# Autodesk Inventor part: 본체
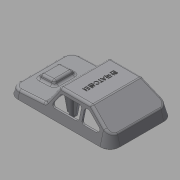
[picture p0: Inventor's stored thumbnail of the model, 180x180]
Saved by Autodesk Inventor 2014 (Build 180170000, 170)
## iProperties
Created: 2015-05
Part Number: 본체
Material: Generic
Document SubType Name: Modeling
Designer: Administrator
Density: 1 g/cm^3
Appearance: Default
Author: Administrator
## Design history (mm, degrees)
sketch "스케치1"
  geometry: L1 (-49, -38)-(49, -38); L2 (61, -26)-(61, 26); L3 (49, 38)-(-49, 38); L4 (-61, 26)-(-61, -26); L5 (-61, -38)-(61, 38); L6 (61, -38)-(-61, 38); A1 r 12 centre (-49, 26) between (-49, 38) and (-61, 26); A2 r 12 centre (-49, -26) between (-61, -26) and (-49, -38); A3 r 12 centre (49, -26) between (49, -38) and (61, -26); A4 r 12 centre (49, 26) between (61, 26) and (49, 38); 3 further points
  constraints: 12 end point, 8 point on circle, 8 point on line, 8 tangent, 4 centre point, 3 equal radius, 3 midpoint, 2 parallel, 1 coincident, 1 horizontal, 1 perpendicular
  dimensions: "d0" = 122 distance of L5.end L6.end; "d1" = 76 distance of L6.start L5.end; "d2" = 12 radius of A1
extrude "돌출1" new body sketch "스케치1" distance "d3" = 30; taper "d4" = -15 deg
sketch "스케치2"
  geometry: L1 (49, 30)-(-49, 30) reference; L2 (-61, 0)-(-52.962, 30) reference; L3 (49, 0)-(-49, 0) reference; L4 (-61, 0)-(-49, 0) reference; L5 (-52.962, 30)-(-49, 30) reference; L6 (-31, 30)-(-61, 10); L7 (-61, 10)-(-61, 30); L8 (-61, 30)-(-31, 30); 1 further point
  constraints: 6 end point, 2 perpendicular, 1 collinear, 1 vertical alignment
  dimensions: "d5" = 20 distance of L6.end L7.end; "d6" = 30 distance of L7.end L6.start
extrude "돌출2" cut sketch "스케치2" stored distance "d7" = 30; taper "d8" = 0 deg
sketch "스케치3"
  geometry: L1 (49, 0)-(61, 0) reference; L2 (61, 0)-(52.962, 30) reference; L3 (49, 30)-(-31, 30) reference; L4 (49, 30)-(52.962, 30) reference; L5 (49, 0)-(-49, 0) reference; L6 (61, 8)-(19, 10.201); L7 (19, 10.201)-(6.628, 30); L8 (6.628, 30)-(61, 30); L9 (61, 30)-(61, 8); 1 further point
  constraints: 8 end point, 1 collinear, 1 parallel, 1 perpendicular, 1 vertical alignment
  dimensions: "d10" = 125 deg angle of L7 L6; "d11" = 3 deg angle of L6 L5; "d12" = 8 distance of L6.start L1.end; "d13" = 42 horizontal distance of L6.end L6.start
extrude "돌출3" cut sketch "스케치3" stored distance "d14" = 30; taper "d15" = 0 deg
sketch "스케치4"
  geometry: L1 (-42.476, 9.267)-(-42.476, 61.267) reference; L2 (-31.476, 48.267)-(-11.476, 48.267); L3 (-11.476, 48.267)-(-11.476, 22.267); L4 (-11.476, 22.267)-(-31.476, 22.267); L5 (-31.476, 22.267)-(-31.476, 48.267); 3 further points
  constraints: 8 end point, 2 midpoint, 2 parallel, 1 horizontal, 1 horizontal alignment, 1 perpendicular
  dimensions: "d16" = 26 distance of L2.end L3.end; "d17" = 20 distance of L3.end L4.end; "d18" = 11 distance between parallel lines of L1 L5
extrude "돌출4" join sketch "스케치4" distance "d19" = 5; taper "d20" = -20 deg
fillet "모깎기1" dims "d21" = 3
fillet "모깎기2" dims "d22" = 3
fillet "모깎기3" dims "d23" = 3
fillet "모깎기4" dims "d24" = 3
feature "쉘1" dims "d25" = 2
sketch "스케치5"
  geometry: L1 (-49, 35.929)-(49, 35.929) reference; L2 (58.929, 26)-(58.929, -26) reference; L3 (49, -35.929)-(-49, -35.929) reference; L4 (-58.929, -26)-(-58.929, 26) reference; L5 (49, 36.929)-(-49, 36.929); L6 (-59.929, 26)-(-59.929, -26); L7 (-49, -36.929)-(49, -36.929); L8 (59.929, -26)-(59.929, 26); A1 r 9.929 centre (49, 26) between (58.929, 26) and (49, 35.929) reference; A2 r 9.929 centre (49, -26) between (49, -35.929) and (58.929, -26) reference; A3 r 9.929 centre (-49, -26) between (-58.929, -26) and (-49, -35.929) reference; A4 r 9.929 centre (-49, 26) between (-49, 35.929) and (-58.929, 26) reference; A5 r 10.929 centre (-49, 26) between (-49, 36.929) and (-59.929, 26); A6 r 10.929 centre (-49, -26) between (-59.929, -26) and (-49, -36.929); A7 r 10.929 centre (49, -26) between (49, -36.929) and (59.929, -26); A8 r 10.929 centre (49, 26) between (59.929, 26) and (49, 36.929); 1 further point
  constraints: 8 end point, 8 point on circle, 4 centre point, 7 other
  dimensions: "d26" = 1 distance between parallel lines of L5 L1
extrude "돌출5" join sketch "스케치5" distance "d27" = 1; taper "d28" = 0 deg
sketch "스케치6"
  geometry: L1 (18.172, 11.526)-(7.51, 28.59) reference; L2 (4.965, 30)-(-30.092, 30) reference; L3 (-31.756, 29.496)-(-50.664, 16.891) reference; L4 (10.362, 14.59)-(4.738, 23.59); L5 (2.194, 25)-(-17.77, 25); L6 (-20.77, 13)-(-20.77, 22); L7 (7.818, 10)-(-17.77, 10); L8 (-30.242, 24.496)-(-43.742, 15.496); L9 (-26.986, 25)-(-28.578, 25); L10 (-23.986, 22)-(-23.986, 13); L11 (-26.986, 10)-(-42.078, 10); A1 r 3 centre (7.818, 13) between (7.818, 10) and (10.362, 14.59); A2 r 3 centre (2.194, 22) between (4.738, 23.59) and (2.194, 25); A3 r 3 centre (-17.77, 22) between (-17.77, 25) and (-20.77, 22); A4 r 3 centre (-17.77, 13) between (-20.77, 13) and (-17.77, 10); A5 r 3 centre (-26.986, 13) between (-26.986, 10) and (-23.986, 13); A6 r 3 centre (-26.986, 22) between (-23.986, 22) and (-26.986, 25); A7 r 3 centre (-28.578, 22) between (-28.578, 25) and (-30.242, 24.496); A8 r 3 centre (-42.078, 13) between (-43.742, 15.496) and (-42.078, 10); 7 further points
  constraints: 16 end point, 16 point on circle, 16 tangent, 12 point on line, 8 centre point, 7 equal radius, 5 parallel, 3 perpendicular
  dimensions: "d29" = 5 distance between parallel lines of L2 L5; "d30" = 5 distance between parallel lines of L1 L4; "d31" = 34 distance of point (13.23, 10) point (-20.77, 10); "d32" = 15 distance of point (-20.77, 10) point (-20.77, 25); "d33" = 5 distance between parallel lines of L3 L8; "d34" = 5 distance between parallel lines of L2 L9; "d35" = 15 distance of point (-23.986, 25) point (-23.986, 10); "d36" = 28 distance of point (-23.986, 10) point (-51.986, 10); "d37" = 3 radius of A1
extrude "돌출6" cut sketch "스케치6" stored distance "d38" = 1; taper "d39" = 0 deg
node "작업 평면1"
sketch "스케치7"
  geometry: A1 r 4 centre (21, 0) between (25, 0) and (17, 0); A2 r 4 centre (10, 0) between (14, 0) and (6, 0); A3 r 4 centre (-10, 0) between (-6, 0) and (-14, 0); A4 r 4 centre (-21, 0) between (-17, 0) and (-25, 0); 4 further points
  constraints: 8 point on circle, 4 centre point, 4 horizontal alignment, 14 other
  dimensions: "d41" = 8 diameter of A1; "d42" = 8 diameter of A2; "d43" = 8 diameter of A3; "d44" = 8 diameter of A4; "d45" = 10 distance of A2.centre point (0, 0); "d46" = 20 distance of A3.centre A2.centre; "d47" = 11 distance of A2.centre A1.centre; "d48" = 11 distance of A4.centre A3.centre
extrude "돌출7" join sketch "스케치7" stored distance "d49" = 1; taper "d50" = 0 deg
chamfer "모따기1" distance "d51" = 1; stored, may be unused: second distance "d52" = 2, angle "d53" = 45 deg
sketch "스케치8"
  geometry: C1 r 3 at (-40, 0); C2 r 3 at (40, 0); C3 r 3 at (0, 22); C4 r 3 at (0, -22); 1 further point
  constraints: 4 centre point, 2 horizontal alignment, 2 vertical alignment
  dimensions: "d54" = 6 diameter of C1; "d55" = 6 diameter of C2; "d56" = 6 diameter of C3; "d57" = 6 diameter of C4; "d58" = 40 distance of point (0, 0) C1.centre; "d59" = 40 distance of C2.centre point (0, 0); "d60" = 22 distance of C3.centre point (0, 0); "d61" = 22 distance of point (0, 0) C4.centre
extrude "돌출8" join sketch "스케치8" stored distance "d62" = 1; taper "d63" = 2 deg
node "작업 평면2"
sketch "스케치9"
  geometry: L1 (-45, -1)-(-35, -1); L2 (-35, -1)-(-35, 1); L3 (-35, 1)-(-45, 1); L4 (-45, 1)-(-45, -1); L5 (-45, -1)-(-35, 1); L6 (-35, -1)-(-45, 1); L7 (-5, 21)-(5, 21); L8 (5, 21)-(5, 23); L9 (5, 23)-(-5, 23); L10 (-5, 23)-(-5, 21); L11 (-5, 21)-(5, 23); L12 (5, 21)-(-5, 23); L13 (35, -1)-(45, -1); L14 (45, -1)-(45, 1); L15 (45, 1)-(35, 1); L16 (35, 1)-(35, -1); L17 (35, -1)-(45, 1); L18 (45, -1)-(35, 1); L19 (-5, -23)-(5, -23); L20 (5, -23)-(5, -21); L21 (5, -21)-(-5, -21); L22 (-5, -21)-(-5, -23); L23 (-5, -23)-(5, -21); L24 (5, -23)-(-5, -21); C1 r 3 at (-40, 0) reference; C2 r 3 at (0, 22) reference; C3 r 3 at (40, 0) reference; C4 r 3 at (0, -22) reference; 1 further point
  constraints: 48 end point, 8 midpoint, 8 parallel, 4 horizontal, 4 perpendicular
  dimensions: "d65" = 10 distance of L1.start L1.end; "d66" = 2 distance of L1.end L2.end; "d67" = 10 distance of L7.start L7.end; "d68" = 2 distance of L7.end L8.end; "d69" = 10 distance of L19.start L19.end; "d70" = 2 distance of L19.end L20.end; "d71" = 10 distance of L13.start L13.end; "d72" = 2 distance of L13.end L14.end
extrude "돌출9" join sketch "스케치9" stored distance "d73" = 1; taper "d74" = 2.5 deg
sketch "스케치11"
  geometry: L1 (45, 2)-(45.429, 11.82) reference; L2 (35, 2)-(34.546, 12.39) reference; L3 (43, 0)-(43.07, 2) reference; L4 (37, 0)-(36.93, 2) reference; L5 (46.675, 11.755)-(34.533, 12.391) reference; L6 (47.906, 9.978)-(47.579, 11.049) reference; L7 (45, 2)-(46.72, 11.753); L8 (45.429, 11.82)-(46.72, 11.753); L9 (-49, 0)-(49, 0) reference; L10 (35, 2)-(33.155, 12.463); L11 (34.546, 12.39)-(33.155, 12.463); A1 r 1 centre (46.623, 10.756) between (47.579, 11.049) and (46.675, 11.755) reference; A2 r 5 centre (52.688, 11.44) between (47.906, 9.978) and (52.426, 6.447) reference; 1 further point
  constraints: 8 end point, 3 collinear, 1 point on line
  dimensions: "d76" = 80 deg angle of L7 L9; "d82" = 80 deg angle of L10 L9
extrude "돌출10" join sketch "스케치11" stored distance "d77" = 1; taper "d78" = 0 deg
sketch "스케치12"
  geometry: L1 (-45, 2)-(-46.719, 11.752) reference; L2 (-45.429, 11.82)-(-45, 2) reference; L3 (-46.675, 11.755)-(-45.429, 11.82) reference; A1 r 1 centre (-46.623, 10.756) between (-46.675, 11.755) and (-46.719, 11.752) reference; 1 further point
extrude "돌출11" join sketch "스케치12" stored distance "d79" = 1; taper "d80" = 0 deg
extrude "돌출12" join sketch "스케치11" stored distance "d83" = 1; taper "d84" = 0 deg
extrude "돌출13" join sketch "스케치11" stored distance "d85" = 1; taper "d86" = 0 deg
sketch "스케치13"
  geometry: L1 (-45, 2)-(-45.69, 17.803) reference; L2 (-35, 2)-(-33.969, 25.617) reference; L3 (-35, 2)-(-37.098, 2) reference; L4 (-42.902, 2)-(-45, 2) reference; L5 (49, 0)-(-49, 0) reference; L6 (-49.555, 15.226)-(-30.646, 27.832) reference; L7 (-45, 2)-(-47.566, 16.552); L8 (-35, 2)-(-30.426, 27.943); L9 (-30.092, 28)-(4.965, 28) reference; A1 r 1 centre (-30.092, 27) between (-30.092, 28) and (-30.646, 27.832) reference; 1 further point
  constraints: 4 end point, 1 point on circle, 1 point on line
  dimensions: "d87" = 80 deg angle of L8 L5; "d88" = 80 deg angle of L7 L5
extrude "돌출14" join sketch "스케치13" stored distance "d89" = 1; taper "d90" = 0 deg
extrude "돌출15" join sketch "스케치13" stored distance "d91" = 1; taper "d92" = 0 deg
extrude "돌출16" join sketch "스케치13" stored distance "d93" = 1; taper "d94" = 0 deg
extrude "돌출17" join sketch "스케치13" stored distance "d95" = 1; taper "d96" = 0 deg
node "작업 평면4"
sketch "스케치14"
  geometry: L1 (16.476, 10.466)-(5.813, 27.53) reference; L2 (4.965, 28)-(-30.092, 28) reference; L3 (-5, 2)-(-6.135, 28) reference; L4 (5, 2)-(6.095, 27.079) reference; L5 (-49, 0)-(49, 0) reference; L6 (5, 2)-(8.69, 22.927); L7 (-5, 2)-(-9.585, 28); 1 further point
  constraints: 4 end point, 2 point on line
  dimensions: "d98" = 80 deg angle of L6 L5; "d99" = 80 deg angle of L5 L7
extrude "돌출18" join sketch "스케치14" stored distance "d100" = 1; taper "d101" = 0 deg
extrude "돌출19" join sketch "스케치14" stored distance "d102" = 1; taper "d103" = 0 deg
extrude "돌출20" join sketch "스케치14" stored distance "d104" = 1; taper "d105" = 0 deg
extrude "돌출21" join sketch "스케치14" stored distance "d106" = 1; taper "d107" = 0 deg
node "작업 평면5"
sketch "스케치15"
  geometry: L1 (-5, 2)-(-6.135, 28) reference; L2 (5, 2)-(6.095, 27.079) reference; L3 (-30.092, 28)-(4.965, 28) reference; L4 (5.813, 27.53)-(16.476, 10.466) reference; L5 (49, 0)-(-49, 0) reference; L6 (-5, 2)-(-9.585, 28); L7 (5, 2)-(8.69, 22.927); 1 further point
  constraints: 4 end point, 2 point on line
  dimensions: "d109" = 80 deg angle of L7 L5; "d110" = 80 deg angle of L5 L6
extrude "돌출22" join sketch "스케치15" stored distance "d111" = 1; taper "d112" = 0 deg
extrude "돌출23" join sketch "스케치15" stored distance "d113" = 1; taper "d114" = 0 deg
extrude "돌출24" join sketch "스케치15" stored distance "d115" = 1; taper "d116" = 0 deg
extrude "돌출25" join sketch "스케치15" stored distance "d117" = 1; taper "d118" = 0 deg
sketch "스케치16"
  geometry: L1 (61, 26)-(61, -26) reference; 2 further points
  constraints: 1 horizontal alignment, 1 other
  dimensions: "d119" = 50 distance from line of L1 point (11, 0)
feature "엠보싱1" sketch "스케치16" dims "d120" = 0.5, "d121" = 0
node "솔리드1"
node "투영된 루프1"
node "투영된 루프2"
node "투영된 루프3"
node "투영된 루프4"
other parameters: "d40" = -63, "d64" = 2, "d97" = -22, "d108" = 22
